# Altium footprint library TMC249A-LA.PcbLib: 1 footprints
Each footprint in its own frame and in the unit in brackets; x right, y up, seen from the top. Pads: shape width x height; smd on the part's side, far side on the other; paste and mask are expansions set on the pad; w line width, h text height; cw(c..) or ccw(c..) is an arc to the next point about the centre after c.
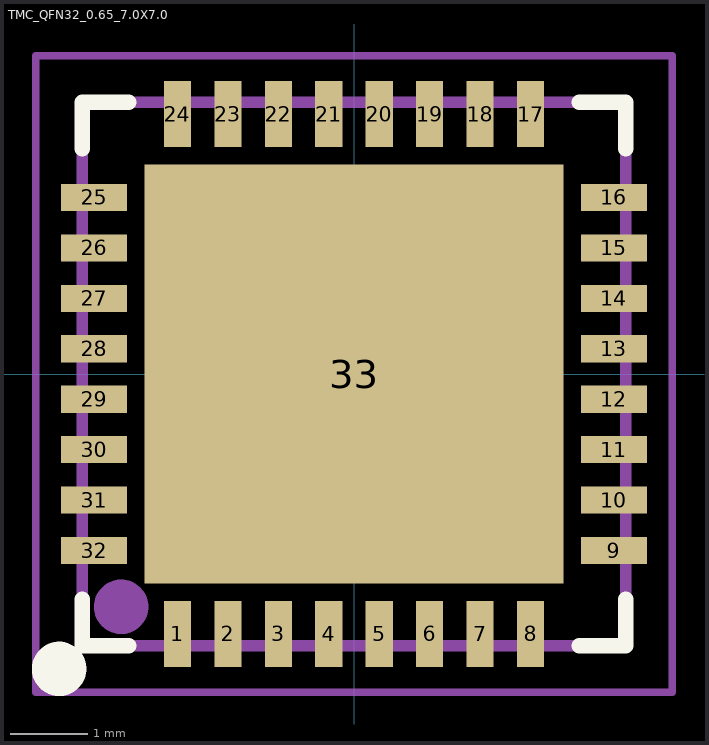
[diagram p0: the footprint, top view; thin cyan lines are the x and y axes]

## TMC_QFN32_0.65_7.0X7.0 [mm]
pads (33):
  rect 0.35x0.85 smd: 1(-2.275,-3.35) 2(-1.625,-3.35) 3(-0.975,-3.35) 4(-0.325,-3.35) 5(0.325,-3.35) 6(0.975,-3.35) 7(1.625,-3.35) 8(2.275,-3.35) 17(2.275,3.35) 18(1.625,3.35) 19(0.975,3.35) 20(0.325,3.35) 21(-0.325,3.35) 22(-0.975,3.35) 23(-1.625,3.35) 24(-2.275,3.35)
  rect 0.85x0.35 smd: 9(3.35,-2.275) 10(3.35,-1.625) 11(3.35,-0.975) 12(3.35,-0.325) 13(3.35,0.325) 14(3.35,0.975) 15(3.35,1.625) 16(3.35,2.275) 25(-3.35,2.275) 26(-3.35,1.625) 27(-3.35,0.975) 28(-3.35,0.325) 29(-3.35,-0.325) 30(-3.35,-0.975) 31(-3.35,-1.625) 32(-3.35,-2.275)
  rrect0% 5.4x5.4 smd paste-254: 33(0,0)
L26-Silk Screen Top (Multiple PADS layers...):
  circle w0.5: c-3.8,-3.8 r0.1
  lines w0.2: -3.5,-2.9 -3.5,-3.5 -2.9,-3.5 ; -3.5,2.9 -3.5,3.5 -2.9,3.5 ; 2.9,-3.5 3.5,-3.5 3.5,-2.9 ; 2.9,3.5 3.5,3.5 3.5,2.9
L23-Paste Mask Top (Multiple PADS layers...):
  region: 0.2,2.2 2.2,2.2 2.2,0.3 0.2,0.3
  region: -2.2,2.2 -0.2,2.2 -0.2,0.3 -2.2,0.3
  region: -2.2,-0.3 -0.2,-0.3 -0.2,-2.2 -2.2,-2.2
  region: 0.2,-0.3 2.2,-0.3 2.2,-2.2 0.2,-2.2
L13:
  circle w0.5: c-3,-3 r0.1
  lines w0.15: -3.5,-3.5 3.5,-3.5 3.5,3.5 -3.5,3.5 -3.5,-3.5
L15 (Multiple PADS layers...):
  lines w0.1: -4.1,-4.1 4.1,-4.1 4.1,4.1 -4.1,4.1 -4.1,-4.1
